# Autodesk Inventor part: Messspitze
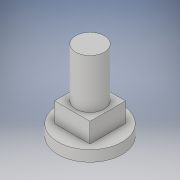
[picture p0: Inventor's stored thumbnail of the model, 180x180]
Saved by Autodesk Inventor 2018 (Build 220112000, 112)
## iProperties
Created: 2018-09
Part Number: Messspitze
Material: Generisch
Document SubType Name: Modeling
Designer: mathes
Density: 1 g/cm^3
Appearance: Vorgabe
Author: mathes
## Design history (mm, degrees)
sketch "Skizze1"
  geometry: C1 r 6.5 at (0, 0); 1 further point
  constraints: 1 centre point, 1 coincident
  dimensions: "d0" = 13 diameter of C1
extrude "Extrusion1" new body sketch "Skizze1" distance "d1" = 2.2; taper "d2" = 0 deg
sketch "Skizze2"
  geometry: L1 (-3.6, 3.6)-(3.6, 3.6); L2 (3.6, 3.6)-(3.6, -3.6); L3 (3.6, -3.6)-(-3.6, -3.6); L4 (-3.6, -3.6)-(-3.6, 3.6); 1 further point
  constraints: 8 end point, 2 parallel, 1 horizontal, 1 perpendicular
  dimensions: "d9" = 3.6 distance from line of point (0, 0) L2; "d10" = 7.2 distance of L2.end L3.end; "d11" = 3.6 distance from line of point (0, 0) L1; "d12" = 3.6 distance from line of L3 point (0, 0)
extrude "Extrusion2" join sketch "Skizze2" distance "d4" = 14; taper "d5" = 0 deg
sketch "Skizze4"
  geometry: C1 r 2.9 at (0, 0); C2 r 6.022 at (0, 0); 1 further point
  constraints: 2 centre point, 2 coincident
  dimensions: "d13" = 5.8 diameter of C1
extrude "Extrusion4" cut sketch "Skizze4" distance "d14" = 10; taper "d15" = 0 deg
node "Volumenkörper1"
